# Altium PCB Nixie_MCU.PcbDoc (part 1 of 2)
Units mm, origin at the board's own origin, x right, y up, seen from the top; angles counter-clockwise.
Board outline 188 x 42 mm, 4 copper layers (Signal Layer 1, Layer 1, Layer 2, Bottom Layer), stack 1.466 mm thick; 180 components, 100 nets, 460 pads, 258 vias.
Unrouted connection lines stored in the file: 2.
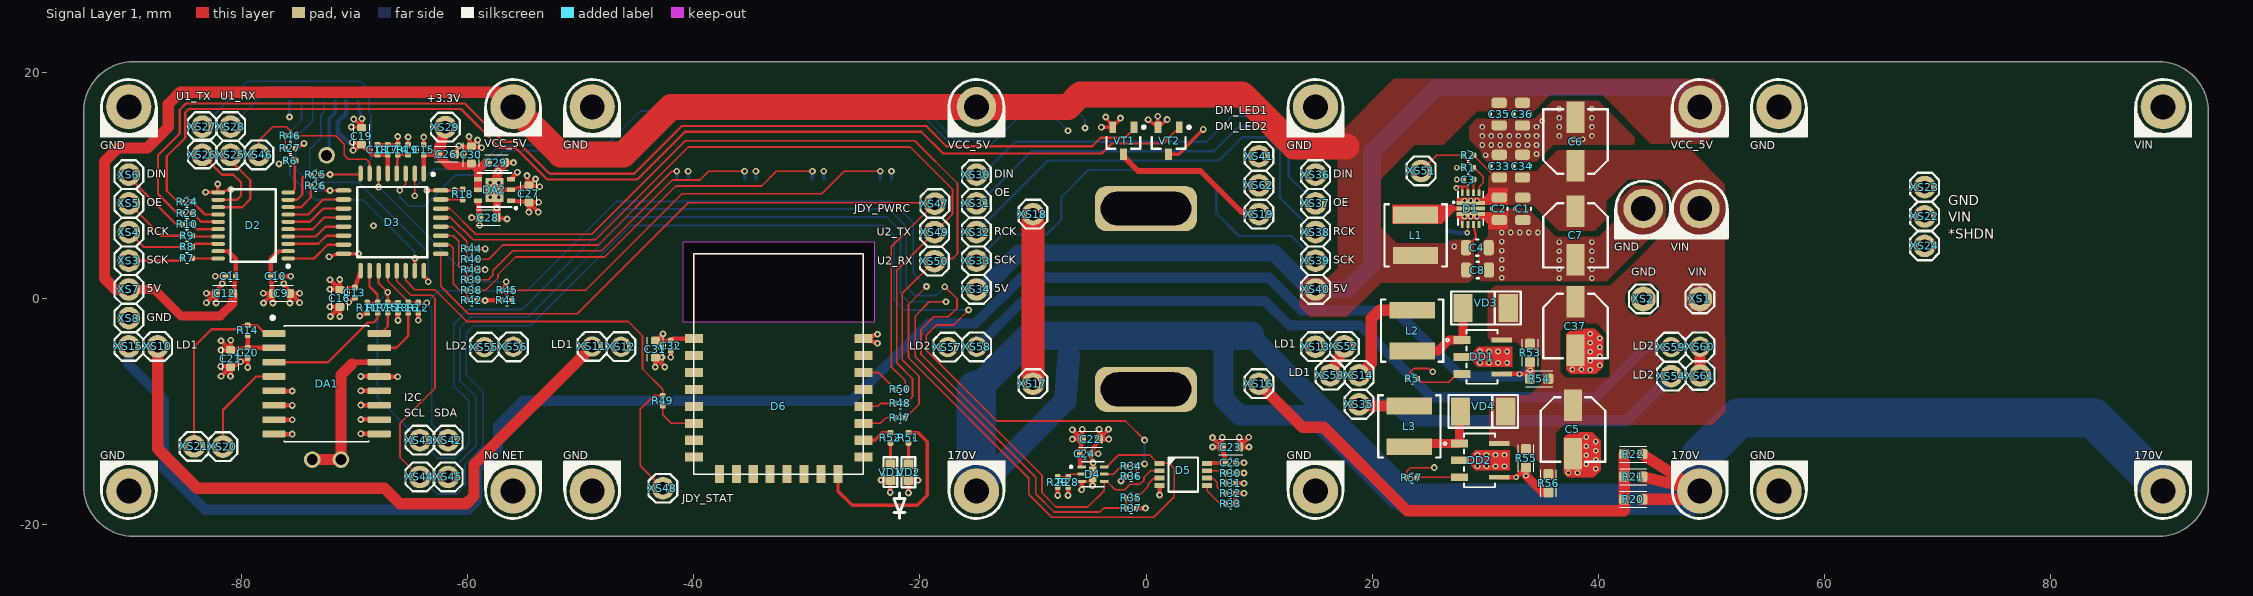
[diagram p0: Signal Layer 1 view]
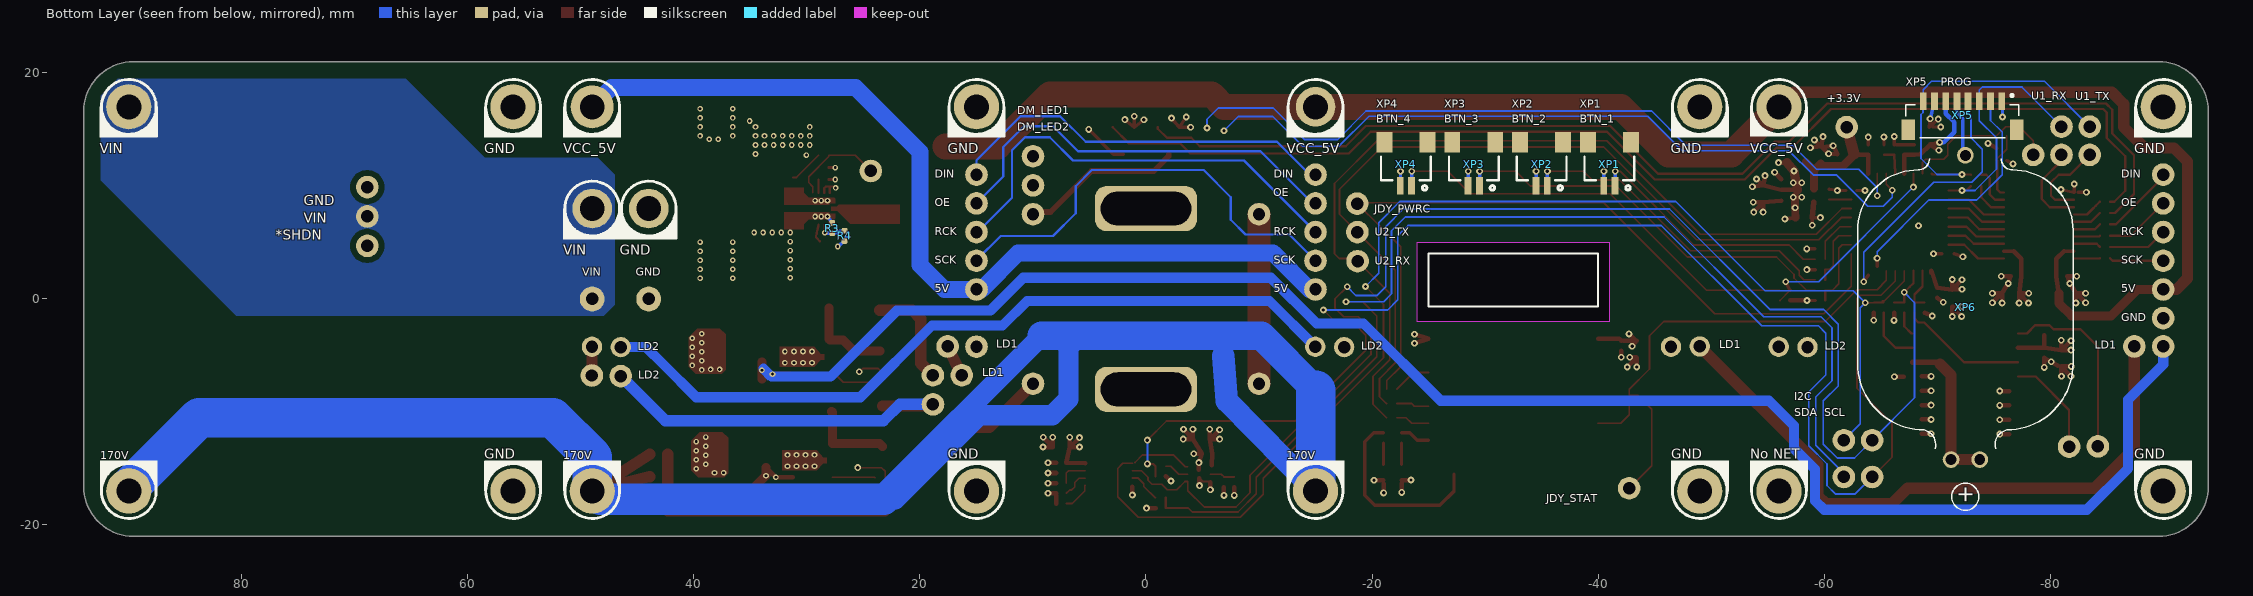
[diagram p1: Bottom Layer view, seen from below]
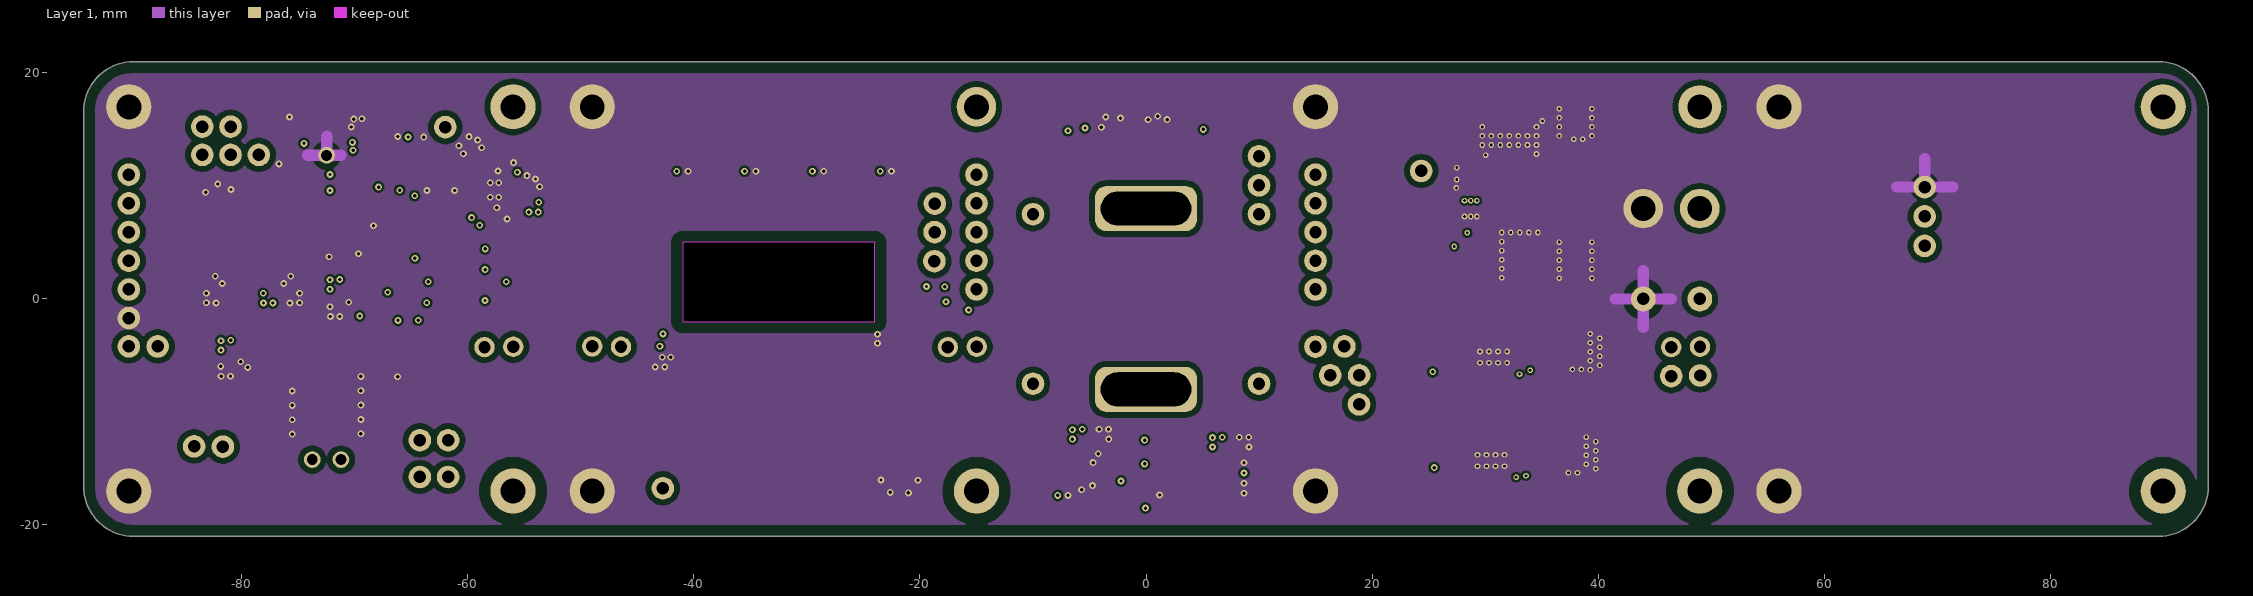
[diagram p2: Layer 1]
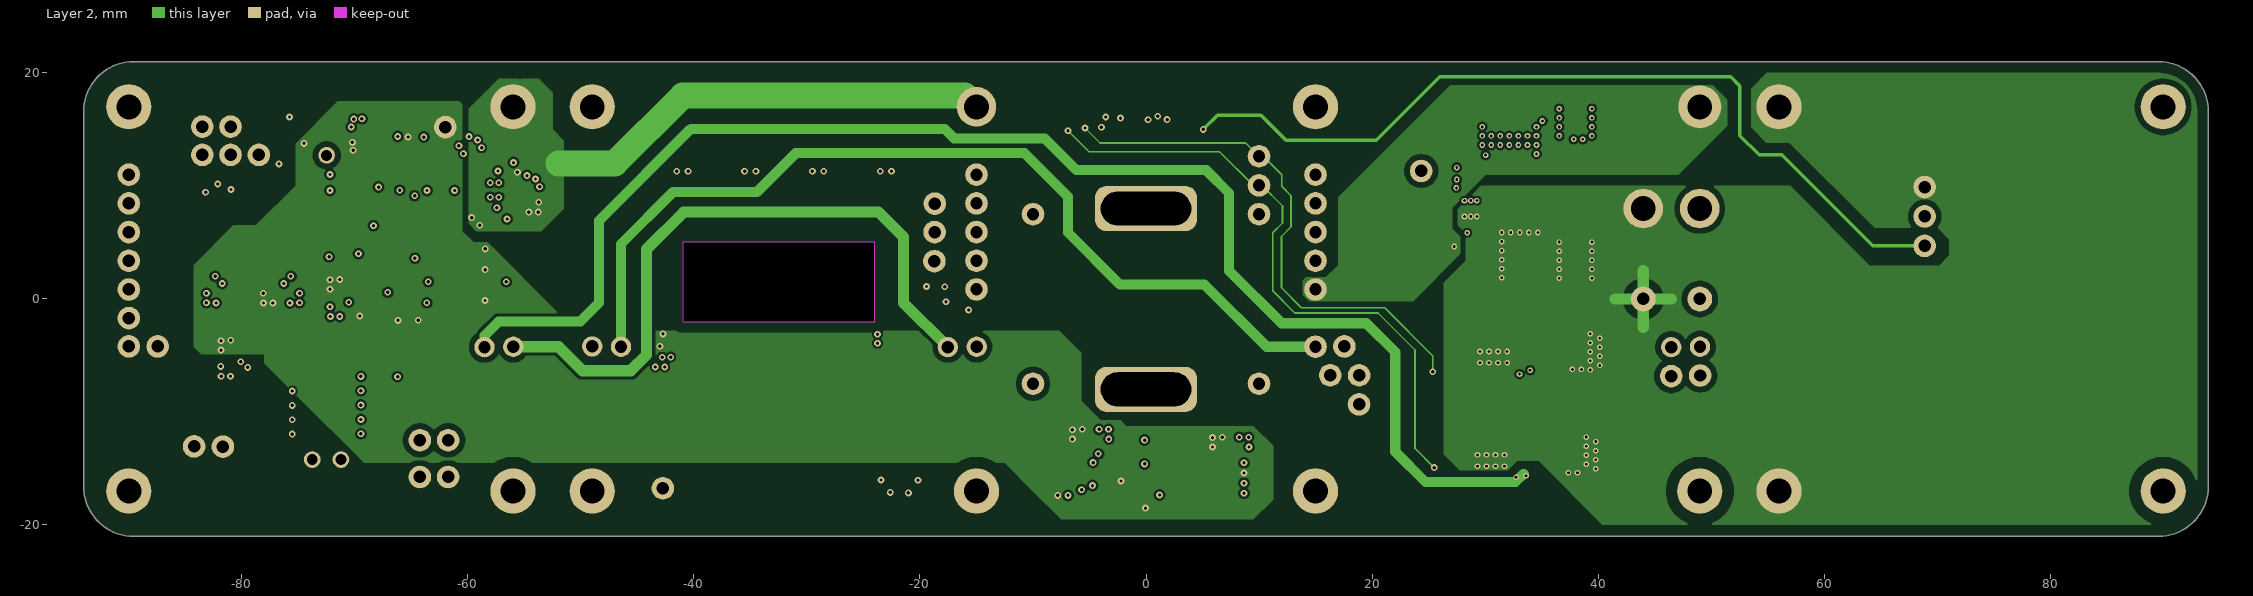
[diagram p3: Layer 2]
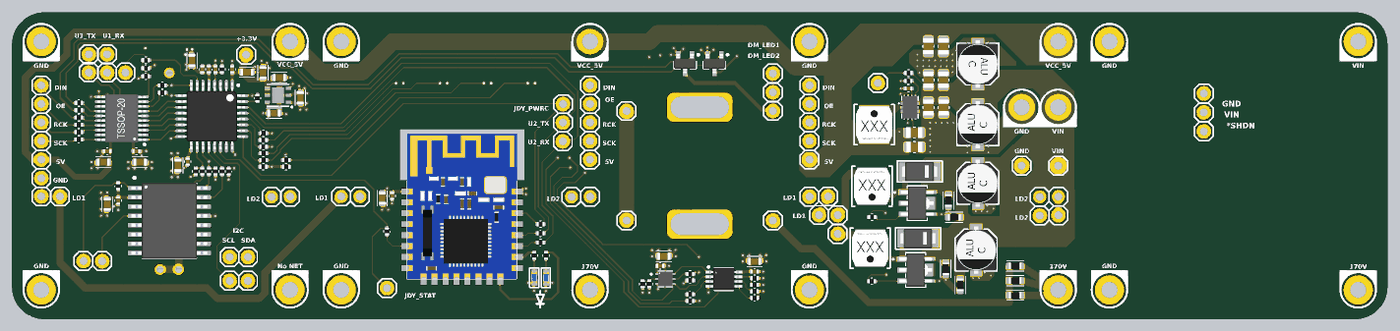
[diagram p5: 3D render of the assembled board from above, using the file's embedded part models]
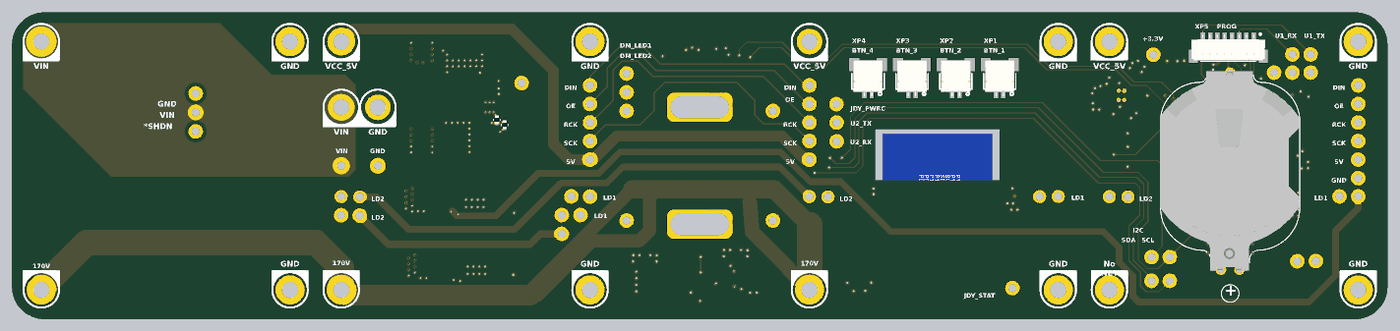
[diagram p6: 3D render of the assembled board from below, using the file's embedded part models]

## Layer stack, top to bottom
Top Solder: solder mask 0.01, Solder Resist, Dk 3.5
Signal Layer 1: signal copper 0.018
Dielectric 2: prepreg 0.115, FR4 2116, Dk 4.2
Layer 1: signal copper 0.018
Dielectric 1: core 1.164, FR4 Tg150, Dk 4.1
Layer 2: signal copper 0.018
Dielectric 3: prepreg 0.115, FR4 2116, Dk 4.1
Bottom Layer: signal copper 0.018
Bottom Solder: solder mask 0.01, Solder Resist, Dk 3.5

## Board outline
-94,-16.586 ccw(c-89.586,-16.586) -89.586,-21 89.586,-21 ccw(c89.586,-16.586) 94,-16.586 94,16.586 ccw(c89.586,16.586) 89.586,21 -89.586,21 ccw(c-89.586,16.586) -94,16.586
cut-out: -41,-2 -24,-2 -24,5 -41,5

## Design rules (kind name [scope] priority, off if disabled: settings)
BoardOutlineClearance [All] p1: gap=1 ignorepadtopadclearanceinfootprint=FALSE
Clearance [All] p1: gap=0.3 ignorepadtopadclearanceinfootprint=FALSE except(0.15: SMDPad-SMDPad SMDPad-THPad SMDPad-Via SMDPad-Fill SMDPad-Poly SMDPad-Region SMDPad-Text SMDPad-Hole; 0.2: Arc-SMDPad Track-SMDPad Via-Via Via-Fill Via-Poly Via-Region Via-Text Via-Hole Fill-Fill Fill-Poly Fill-Region Poly-Poly Poly-Region Region-Region; 0.25: Fill-Text Fill-Hole Poly-Text Poly-Hole Region-Text Region-Hole Text-Text Text-Hole; 0.5: THPad-THPad THPad-Via THPad-Fill THPad-Poly THPad-Region THPad-Text THPad-Hole)
ComponentClearance [All] p1: gap=0 collisioncheckmode=3 verticalgap=0 showdistances=FALSE
DiffPairsRouting [All] p1: maxlimit=0.254 minlimit=0.254 mostfreqgap=0.254 substack1={13A373E5-A3F0-4F58-9A2E-6A10E35ADB22} toplayer_{13a373e5-a3f0-4f58-9a2e-6a10e35adb22}_minwidth=0.381 toplayer_{13a373e5-a3f0-4f58-9a2e-6a10e35adb22}_maxwidth=0.381 toplayer_{13a373e5-a3f0-4f58-9a2e-6a10e35adb22}_prefwidth=0.381 midlayer1_{13a373e5-a3f0-4f58-9a2e-6a10e35adb22}_minwidth=0.381 midlayer1_{13a373e5-a3f0-4f58-9a2e-6a10e35adb22}_maxwidth=0.381 midlayer1_{13a373e5-a3f0-4f58-9a2e-6a10e35adb22}_prefwidth=0.381 midlayer2_{13a373e5-a3f0-4f58-9a2e-6a10e35adb22}_minwidth=0.381 midlayer2_{13a373e5-a3f0-4f58-9a2e-6a10e35adb22}_maxwidth=0.381 midlayer2_{13a373e5-a3f0-4f58-9a2e-6a10e35adb22}_prefwidth=0.381 bottomlayer_{13a373e5-a3f0-4f58-9a2e-6a10e35adb22}_minwidth=0.381 bottomlayer_{13a373e5-a3f0-4f58-9a2e-6a10e35adb22}_maxwidth=0.381 bottomlayer_{13a373e5-a3f0-4f58-9a2e-6a10e35adb22}_prefwidth=0.381 toplayer_minwidth=0.381 toplayer_maxwidth=0.381 toplayer_prefwidth=0.381 midlayer1_minwidth=0.381 midlayer1_maxwidth=0.381 midlayer1_prefwidth=0.381 midlayer2_minwidth=0.381 midlayer2_maxwidth=0.381 midlayer2_prefwidth=0.381 bottomlayer_minwidth=0.381 bottomlayer_maxwidth=0.381 bottomlayer_prefwidth=0.381 substack2={8E264451-6B6F-4AEF-BE25-3FA629468181} toplayer_{8e264451-6b6f-4aef-be25-3fa629468181}_minwidth=0.381 toplayer_{8e264451-6b6f-4aef-be25-3fa629468181}_maxwidth=0.381 toplayer_{8e264451-6b6f-4aef-be25-3fa629468181}_prefwidth=0.381 midlayer1_{8e264451-6b6f-4aef-be25-3fa629468181}_minwidth=0.381 midlayer1_{8e264451-6b6f-4aef-be25-3fa629468181}_maxwidth=0.381 midlayer1_{8e264451-6b6f-4aef-be25-3fa629468181}_prefwidth=0.381 midlayer2_{8e264451-6b6f-4aef-be25-3fa629468181}_minwidth=0.381 midlayer2_{8e264451-6b6f-4aef-be25-3fa629468181}_maxwidth=0.381 midlayer2_{8e264451-6b6f-4aef-be25-3fa629468181}_prefwidth=0.381 bottomlayer_{8e264451-6b6f-4aef-be25-3fa629468181}_minwidth=0.381 bottomlayer_{8e264451-6b6f-4aef-be25-3fa629468181}_maxwidth=0.381 bottomlayer_{8e264451-6b6f-4aef-be25-3fa629468181}_prefwidth=0.381 substack3={4B01B843-C838-4E2A-A504-E6D8B842CAE6} toplayer_{4b01b843-c838-4e2a-a504-e6d8b842cae6}_minwidth=0.381 toplayer_{4b01b843-c838-4e2a-a504-e6d8b842cae6}_maxwidth=0.381 toplayer_{4b01b843-c838-4e2a-a504-e6d8b842cae6}_prefwidth=0.381 midlayer1_{4b01b843-c838-4e2a-a504-e6d8b842cae6}_minwidth=0.381 midlayer1_{4b01b843-c838-4e2a-a504-e6d8b842cae6}_maxwidth=0.381 midlayer1_{4b01b843-c838-4e2a-a504-e6d8b842cae6}_prefwidth=0.381 midlayer2_{4b01b843-c838-4e2a-a504-e6d8b842cae6}_minwidth=0.381 midlayer2_{4b01b843-c838-4e2a-a504-e6d8b842cae6}_maxwidth=0.381 midlayer2_{4b01b843-c838-4e2a-a504-e6d8b842cae6}_prefwidth=0.381 bottomlayer_{4b01b843-c838-4e2a-a504-e6d8b842cae6}_minwidth=0.381 bottomlayer_{4b01b843-c838-4e2a-a504-e6d8b842cae6}_maxwidth=0.381 bottomlayer_{4b01b843-c838-4e2a-a504-e6d8b842cae6}_prefwidth=0.381 substack4={99483382-A1EF-4ECF-B319-A0B368B90AE1} toplayer_{99483382-a1ef-4ecf-b319-a0b368b90ae1}_minwidth=0.381 toplayer_{99483382-a1ef-4ecf-b319-a0b368b90ae1}_maxwidth=0.381 toplayer_{99483382-a1ef-4ecf-b319-a0b368b90ae1}_prefwidth=0.381 midlayer1_{99483382-a1ef-4ecf-b319-a0b368b90ae1}_minwidth=0.381 midlayer1_{99483382-a1ef-4ecf-b319-a0b368b90ae1}_maxwidth=0.381 midlayer1_{99483382-a1ef-4ecf-b319-a0b368b90ae1}_prefwidth=0.381 midlayer2_{99483382-a1ef-4ecf-b319-a0b368b90ae1}_minwidth=0.381 midlayer2_{99483382-a1ef-4ecf-b319-a0b368b90ae1}_maxwidth=0.381 midlayer2_{99483382-a1ef-4ecf-b319-a0b368b90ae1}_prefwidth=0.381 bottomlayer_{99483382-a1ef-4ecf-b319-a0b368b90ae1}_minwidth=0.381 bottomlayer_{99483382-a1ef-4ecf-b319-a0b368b90ae1}_maxwidth=0.381 bottomlayer_{99483382-a1ef-4ecf-b319-a0b368b90ae1}_prefwidth=0.381 substack5={F395EEA6-3FEA-43CE-B6E0-8CB6C0DE68A3} toplayer_{f395eea6-3fea-43ce-b6e0-8cb6c0de68a3}_minwidth=0.381 toplayer_{f395eea6-3fea-43ce-b6e0-8cb6c0de68a3}_maxwidth=0.381 toplayer_{f395eea6-3fea-43ce-b6e0-8cb6c0de68a3}_prefwidth=0.381 midlayer1_{f395eea6-3fea-43ce-b6e0-8cb6c0de68a3}_minwidth=0.381 midlayer1_{f395eea6-3fea-43ce-b6e0-8cb6c0de68a3}_maxwidth=0.381 midlayer1_{f395eea6-3fea-43ce-b6e0-8cb6c0de68a3}_prefwidth=0.381 midlayer2_{f395eea6-3fea-43ce-b6e0-8cb6c0de68a3}_minwidth=0.381 midlayer2_{f395eea6-3fea-43ce-b6e0-8cb6c0de68a3}_maxwidth=0.381 midlayer2_{f395eea6-3fea-43ce-b6e0-8cb6c0de68a3}_prefwidth=0.381 bottomlayer_{f395eea6-3fea-43ce-b6e0-8cb6c0de68a3}_minwidth=0.381 bottomlayer_{f395eea6-3fea-43ce-b6e0-8cb6c0de68a3}_maxwidth=0.381 bottomlayer_{f395eea6-3fea-43ce-b6e0-8cb6c0de68a3}_prefwidth=0.381 maxuncoupledlength=12.7
Height [All] p1: minheight=0 maxheight=1000 prefheight=0
MinimumSolderMaskSliver [All] p1: minsoldermaskwidth=0.2
PlaneClearance [All] p1: clearance=0.5
PlaneConnect [All] p1: planeconnectstyle=Relief reliefexpansion=0.5 reliefentries=4 reliefconductorwidth=0.25 reliefairgap=0.25
PolygonConnect PolygonConnect_VIA [IsVia] p1: connectstyle=Direct reliefconductorwidth=0.3 reliefentries=4 polygonreliefangle="45 Angle" airgapwidth=0.25
PolygonConnect [All] p2: connectstyle=Direct reliefconductorwidth=0.3 reliefentries=4 polygonreliefangle="90 Angle" airgapwidth=0.25
RoutingCorners [All] p1: cornerstyle=45-Degree minsetback=2.5 maxsetback=2.5
RoutingVias [All] p1: holewidth=0.3 width=0.6 viastyle="Through Hole" minholewidth=0.2 minwidth=0.5 maxholewidth=0.7 maxwidth=1.2
SilkToSilkClearance [All] p1: silktosilkclearance=0.2
SilkToSolderMaskClearance [IsPad] p1: minsilkscreentomaskgap=0.2 clearancetoexposedcopper=TRUE
SolderMaskExpansion [All] p1: expansion=0.075 istentingtop=FALSE
Width [All] p1: maxlimit=10 minlimit=0.125 preferedwidth=0.25 substack1={13A373E5-A3F0-4F58-9A2E-6A10E35ADB22} toplayer_{13a373e5-a3f0-4f58-9a2e-6a10e35adb22}_minwidth=0.15 toplayer_{13a373e5-a3f0-4f58-9a2e-6a10e35adb22}_maxwidth=2.5 midlayer1_{13a373e5-a3f0-4f58-9a2e-6a10e35adb22}_minwidth=0.15 midlayer1_{13a373e5-a3f0-4f58-9a2e-6a10e35adb22}_maxwidth=2.5 midlayer2_{13a373e5-a3f0-4f58-9a2e-6a10e35adb22}_minwidth=0.15 midlayer2_{13a373e5-a3f0-4f58-9a2e-6a10e35adb22}_maxwidth=2.5 bottomlayer_{13a373e5-a3f0-4f58-9a2e-6a10e35adb22}_minwidth=0.15 bottomlayer_{13a373e5-a3f0-4f58-9a2e-6a10e35adb22}_maxwidth=2.5 substack2={8E264451-6B6F-4AEF-BE25-3FA629468181} toplayer_{8e264451-6b6f-4aef-be25-3fa629468181}_minwidth=0.15 toplayer_{8e264451-6b6f-4aef-be25-3fa629468181}_maxwidth=2.5 midlayer1_{8e264451-6b6f-4aef-be25-3fa629468181}_minwidth=0.15 midlayer1_{8e264451-6b6f-4aef-be25-3fa629468181}_maxwidth=2.5 midlayer2_{8e264451-6b6f-4aef-be25-3fa629468181}_minwidth=0.15 midlayer2_{8e264451-6b6f-4aef-be25-3fa629468181}_maxwidth=2.5 bottomlayer_{8e264451-6b6f-4aef-be25-3fa629468181}_minwidth=0.15 bottomlayer_{8e264451-6b6f-4aef-be25-3fa629468181}_maxwidth=2.5 substack3={4B01B843-C838-4E2A-A504-E6D8B842CAE6} toplayer_{4b01b843-c838-4e2a-a504-e6d8b842cae6}_minwidth=0.15 toplayer_{4b01b843-c838-4e2a-a504-e6d8b842cae6}_maxwidth=2.5 midlayer1_{4b01b843-c838-4e2a-a504-e6d8b842cae6}_minwidth=0.15 midlayer1_{4b01b843-c838-4e2a-a504-e6d8b842cae6}_maxwidth=2.5 midlayer2_{4b01b843-c838-4e2a-a504-e6d8b842cae6}_minwidth=0.15 midlayer2_{4b01b843-c838-4e2a-a504-e6d8b842cae6}_maxwidth=2.5 bottomlayer_{4b01b843-c838-4e2a-a504-e6d8b842cae6}_minwidth=0.15 bottomlayer_{4b01b843-c838-4e2a-a504-e6d8b842cae6}_maxwidth=2.5 substack4={99483382-A1EF-4ECF-B319-A0B368B90AE1} toplayer_{99483382-a1ef-4ecf-b319-a0b368b90ae1}_minwidth=0.15 toplayer_{99483382-a1ef-4ecf-b319-a0b368b90ae1}_maxwidth=2.5 midlayer1_{99483382-a1ef-4ecf-b319-a0b368b90ae1}_minwidth=0.15 midlayer1_{99483382-a1ef-4ecf-b319-a0b368b90ae1}_maxwidth=2.5 midlayer2_{99483382-a1ef-4ecf-b319-a0b368b90ae1}_minwidth=0.15 midlayer2_{99483382-a1ef-4ecf-b319-a0b368b90ae1}_maxwidth=2.5 bottomlayer_{99483382-a1ef-4ecf-b319-a0b368b90ae1}_minwidth=0.15 bottomlayer_{99483382-a1ef-4ecf-b319-a0b368b90ae1}_maxwidth=2.5 substack5={F395EEA6-3FEA-43CE-B6E0-8CB6C0DE68A3} toplayer_{f395eea6-3fea-43ce-b6e0-8cb6c0de68a3}_minwidth=0.15 toplayer_{f395eea6-3fea-43ce-b6e0-8cb6c0de68a3}_maxwidth=2.5 midlayer1_{f395eea6-3fea-43ce-b6e0-8cb6c0de68a3}_minwidth=0.15 midlayer1_{f395eea6-3fea-43ce-b6e0-8cb6c0de68a3}_maxwidth=2.5 midlayer2_{f395eea6-3fea-43ce-b6e0-8cb6c0de68a3}_minwidth=0.15 midlayer2_{f395eea6-3fea-43ce-b6e0-8cb6c0de68a3}_maxwidth=2.5 bottomlayer_{f395eea6-3fea-43ce-b6e0-8cb6c0de68a3}_minwidth=0.15 bottomlayer_{f395eea6-3fea-43ce-b6e0-8cb6c0de68a3}_maxwidth=2.5
21 further rules are at their usual default settings.

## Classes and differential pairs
component class Nixie_MCU: C9 C10 C11 C12 C14 C20 C21 C22 C23 C24 C25 C31 C32 D2 D3 D4 D5 D6 DA1 R6 R7 R8 R9 R10 R11 R12 R13 R14 R15 R16 R17 R18 R19 R25 R26 R27 R28 R29 R30 R31 R32 R33 R34 R35 R36 R37 R38 R39 R40 R41 R42 R43 R44 R45 R46 R47 R48 R49 R50 R51 R52 VD1 VD2 XP1 XP2 XP3 XP4 XP5 XP6 XS3 XS4 XS5 XS6 XS20 XS21 XS25 XS26 XS27 XS28 XS30 XS31 XS32 XS33 XS34 XS36 XS37 XS38 XS39 XS40 XS42 XS43 XS44 XS45 XS46 XS47 XS48 XS49 XS50
component class Nixie_MCU_PWR: C1 C2 C3 C4 C5 C6 C7 C8 C13 C15 C16 C17 C18 C19 C26 C27 C28 C29 C30 C33 C34 C35 C36 C37 D1 DA2 DD1 DD2 L1 L2 L3 R1 R2 R3 R4 R5 R20 R21 R22 R23 R24 R53 R54 R55 R56 R57 VD3 VD4 VT1 VT2 XS1 XS2 XS7 XS8 XS10 XS11 XS12 XS13 XS14 XS15 XS16 XS17 XS18 XS19 XS22 XS23 XS24 XS29 XS35 XS41 XS51 XS52 XS53 XS54 XS55 XS56 XS57 XS58 XS59 XS60 XS61 XS62

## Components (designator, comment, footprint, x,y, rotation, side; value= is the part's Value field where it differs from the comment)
C1 "" "CAP: 0805R" 33.342,7.978 r90 top value="22 мкФ"
C2 "" "CAP: 0805R" 31.256,7.979 r90 top value="22 мкФ"
C3 "Ceramic capacitor, 2200 пФ, X7R, ± 10 %, , 0402, -55...+125°C" "CAP: 0402R" 28.523,10.568 r0 top value="2200 пФ"
C4 "" "CAP: 0805R" 29.32,4.538 r180 top value="22 мкФ"
C5 "Aluminium capacitor, 100 мкФ, , ±20%, , 5×5×5.3, -55...+105°C" "CAP: D5H5.8" 37.775,-11.55 r270 top value="100 мкФ"
C6 "Aluminium capacitor, 100 мкФ, , ±20%, , 5×5×5.3, -55...+105°C" "CAP: D5H5.8" 38.01,13.924 r90 top value="100 мкФ"
C7 "Aluminium capacitor, 100 мкФ, , ±20%, , 5×5×5.3, -55...+105°C" "CAP: D5H5.8" 38.01,5.625 r270 top value="100 мкФ"
C8 "" "CAP: 0805R" 29.338,2.558 r180 top value="22 мкФ"
C9 "Ceramic capacitor, 2,2 мкФ, X7R, ±10%, 16V, 0603, -55...+125°C" "CAP: 0603R" -76.5,0.5 r0 top value="2,2 мкФ"
C10 "Ceramic capacitor, 0,1 мкФ, X7R, ± 10 %, , 0402, -55...+125°C" "CAP: 0402R" -77,2 r180 top value="0,1 мкФ"
C11 "Ceramic capacitor, 0,1 мкФ, X7R, ± 10 %, , 0402, -55...+125°C" "CAP: 0402R" -81,2 r0 top value="0,1 мкФ"
C12 "Ceramic capacitor, 2,2 мкФ, X7R, ±10%, 16V, 0603, -55...+125°C" "CAP: 0603R" -81.525,0.5 r180 top value="2,2 мкФ"
C13 "Ceramic capacitor, 0,1 мкФ, X7R, ± 10 %, , 0402, -55...+125°C" "CAP: 0402R" -69.994,0.559 r90 top value="0,1 мкФ"
C14 "Ceramic capacitor, 0,1 мкФ, X7R, ± 10 %, , 0402, -55...+125°C" "CAP: 0402R" -66.2,13.2 r270 top value="0,1 мкФ"
C15 "Ceramic capacitor, 0,1 мкФ, X7R, ± 10 %, , 0402, -55...+125°C" "CAP: 0402R" -63.907,13.198 r270 top value="0,1 мкФ"
C16 "Ceramic capacitor, 10 мкФ, X7R, ±10%, 16V, 0603, -55...+125°C" "CAP: 0603R" -71.334,0.055 r270 top value="10 мкФ"
C17 "Ceramic capacitor, 10 нФ, X7R, ± 10 %, , 0402, -55...+125°C" "CAP: 0402R" -67.1,13.2 r270 top value="10 нФ"
C18 "Ceramic capacitor, 0,1 мкФ, X7R, ± 10 %, , 0402, -55...+125°C" "CAP: 0402R" -68,13.2 r270 top value="0,1 мкФ"
C19 "Ceramic capacitor, 10 мкФ, X7R, ±10%, 16V, 0603, -55...+125°C" "CAP: 0603R" -69.4,14.4 r90 top value="10 мкФ"
C20 "Ceramic capacitor, 0,1 мкФ, X7R, ± 10 %, , 0402, -55...+125°C" "CAP: 0402R" -79.485,-4.772 r90 top value="0,1 мкФ"
C21 "Ceramic capacitor, 2,2 мкФ, X7R, ±10%, 16V, 0603, -55...+125°C" "CAP: 0603R" -80.985,-5.272 r270 top value="2,2 мкФ"
C22 "Ceramic capacitor, 2,2 мкФ, X7R, ±10%, 16V, 0603, -55...+125°C" "CAP: 0603R" -4.9,-12.4 r0 top value="2,2 мкФ"
C23 "Ceramic capacitor, 2,2 мкФ, X7R, ±10%, 16V, 0603, -55...+125°C" "CAP: 0603R" 7.5,-13.1 r0 top value="2,2 мкФ"
C24 "Ceramic capacitor, 0,1 мкФ, X7R, ± 10 %, , 0402, -55...+125°C" "CAP: 0402R" -5.4,-13.7 r180 top value="0,1 мкФ"
C25 "Ceramic capacitor, 0,1 мкФ, X7R, ± 10 %, , 0402, -55...+125°C" "CAP: 0402R" 7.5,-14.5 r180 top value="0,1 мкФ"
C26 "Ceramic capacitor, 10 мкФ, X7R, ±10%, 16V, 0603, -55...+125°C" "CAP: 0603R" -61.899,12.82 r0 top value="10 мкФ"
C27 "Ceramic capacitor, 10 мкФ, X7R, ±10%, 16V, 0603, -55...+125°C" "CAP: 0603R" -54.6,9.3 r90 top value="10 мкФ"
C28 "Ceramic capacitor, 10 мкФ, X7R, ±10%, 16V, 0603, -55...+125°C" "CAP: 0603R" -58.2,7.2 r0 top value="10 мкФ"
C29 "Ceramic capacitor, 10 мкФ, X7R, ±10%, 16V, 0603, -55...+125°C" "CAP: 0603R" -57.473,12.073 r0 top value="10 мкФ"
C30 "Ceramic capacitor, 10 мкФ, X7R, ±10%, 16V, 0603, -55...+125°C" "CAP: 0603R" -59.7,12.75 r90 top value="10 мкФ"
C31 "Ceramic capacitor, 2,2 мкФ, X7R, ±10%, 16V, 0603, -55...+125°C" "CAP: 0603R" -43.416,-4.44 r270 top value="2,2 мкФ"
C32 "Ceramic capacitor, 0,1 мкФ, X7R, ± 10 %, , 0402, -55...+125°C" "CAP: 0402R" -42.04,-4.129 r90 top value="0,1 мкФ"
C33 "" "CAP: 0805R" 31.267,11.755 r270 top value="22 мкФ"
C34 "" "CAP: 0805R" 33.307,11.755 r270 top value="22 мкФ"
C35 "" "CAP: 0805R" 31.247,16.361 r90 top value="22 мкФ"
C36 "" "CAP: 0805R" 33.307,16.356 r90 top value="22 мкФ"
C37 "Aluminium capacitor, 100 мкФ, , ±20%, , 5×5×5.3, -55...+105°C" "CAP: D5H5.8" 38,-2.4 r270 top value="100 мкФ"
D1 "DC/DC buck converter, 3 V to 17 V, 1.25 or 2.5MHz, 0.8 V to 12 V, 2A, -40...+85°C, 3-mm x 2-mm VQFN" 11-VQFN(RGX) 28.727,8 r0 top
D2 "8-Bit Bidirectional Voltage-Level Translator, 24 Mbps, , 1.2 V to 3.6 V on A port and 1.65 V to 5.5 V on B, -40...+105°C, 20-TSSOP" 20-TSSOP -79,6.5 r180 top
D3 "IC microcontroller, 32-Bit, Cortex-M0, 48MHz, 32KB, 4KB, 2.4...3.6V, -40...+85°C, 32-LQFP" 32-LQFP -66.7,6.8 r270 top locked
D4 "Ambient Light Sensor, 1.6 V to 3.6 V, , , , -40…+85, USON (6)" "6-USON (OPT)" -4.7,-15.5 r0 top
D5 "Digital Temperature Sensor, 2.7V to 5.5V, , , , -40…+85, MSOP-8" 8-MSOP 1.2,-14.55 r270 top
D6 "bluetooth module, , , , -40...+85°C," "MOD: JDY-25M" -40,-15.5 r0 top locked
DA1 "Standard Clock Oscillators, , 15pF, ±50ppm, 7*5mm, -40...+85°C" 16-SOIC -72.5,-7.5 r0 top locked
DA2 "LP38693SD-3.3/NOPB" 6-WSON -57.647,9.642 r270 top
DD1 "LED current driver, 6 V to 30 v, , , 1.2A, -40…+125, SOT89-5" 5-SOT-89 29.728,-5.125 r270 top
DD2 "LED current driver, 6 V to 30 v, , , 1.2A, -40…+125, SOT89-5" 5-SOT-89 29.503,-14.275 r270 top
L1 "Fixed inductor, 2,2 мкГн, , , , -40...+125°C" "IND: VLS5045EX" 23.95,5.625 r90 top value="2,2 мкГн"
L2 "Fixed inductor, 100 мкГн, , , , -40...+125°C" "IND: VLS5045EX" 23.45,-2.8 r270 top value="100 мкГн"
L3 "Fixed inductor, 100 мкГн, , , , -40...+125°C" "IND: VLS5045EX" 23.2,-11.275 r270 top value="100 мкГн"
R1 "" "RES: 0402_ASK" 28.52,11.624 r180 top value="Не уст"
R2 "" "RES: 0402_ASK" 28.523,12.704 r180 top value="22 Ом"
R3 "" "RES: 0402_ASK" 27.75,6.275 r90 bottom value="150 кОм"
R4 "" "RES: 0402_ASK" 26.675,5.575 r90 bottom value="560 кОм"
R5 "" "RES: 0402_ASK" 23.55,-7.05 r0 top value="22 Ом"
R6 "" "RES: 0402_ASK" -75.7,12.25 r0 top value="20 кОм"
R7 "" "RES: 0402_ASK" -84.85,3.6 r180 top value="22 Ом"
R8 "" "RES: 0402_ASK" -84.85,4.6 r180 top value="22 Ом"
R9 "" "RES: 0402_ASK" -84.85,5.6 r180 top value="22 Ом"
R10 "" "RES: 0402_ASK" -84.85,6.6 r180 top value="22 Ом"
R11 "" "RES: 0402_ASK" -68.891,-0.77 r90 top value="10 кОм"
R12 "" "RES: 0402_ASK" -64.388,-0.769 r90 top value="10 кОм"
R13 "" "RES: 0402_ASK" -66.187,-0.774 r90 top value="10 кОм"
R14 "" "RES: 0402_ASK" -79.485,-2.772 r90 top value="10 кОм"
R15 "" "RES: 0402_ASK" -67.088,-0.764 r270 top value="22 Ом"
R16 "" "RES: 0402_ASK" -65.286,-0.768 r270 top value="22 Ом"
R17 "" "RES: 0402_ASK" -67.988,-0.766 r270 top value="22 Ом"
R18 "" "RES: 0402_ASK" -60.456,9.253 r90 top value="10 кОм"
R19 "" "RES: 0402_ASK" -65.3,13.2 r270 top value="10 кОм"
R20 "Resistor film, ?, ±1%, 0603, 0.1W, -55...+125°C" "RES: 0603_ASK" 42.325,-17.739 r0 top value=?
R21 "Resistor film, ?, ±1%, 0603, 0.1W, -55...+125°C" "RES: 0603_ASK" 42.325,-15.739 r0 top value=?
R22 "Resistor film, ?, ±1%, 0603, 0.1W, -55...+125°C" "RES: 0603_ASK" 42.325,-13.739 r0 top value=?
R23 "" "RES: 0402_ASK" -84.845,7.603 r0 top value="10 кОм"
R24 "" "RES: 0402_ASK" -84.847,8.606 r0 top value="10 кОм"
R25 "" "RES: 0402_ASK" -73.45,11 r180 top value="Не уст"
R26 "" "RES: 0402_ASK" -73.45,10 r180 top value="Не уст"
R27 "" "RES: 0402_ASK" -75.7,13.352 r0 top value="Не уст"
R28 "" "RES: 0402_ASK" -6.895,-16.196 r90 top value="22 Ом"
R29 "" "RES: 0402_ASK" -7.8,-16.2 r90 top value="Не уст"
R30 "" "RES: 0402_ASK" 7.5,-15.4 r0 top value="Не уст"
R31 "" "RES: 0402_ASK" 7.5,-16.3 r0 top value="22 Ом"
R32 "" "RES: 0402_ASK" 7.5,-17.2 r0 top value="22 Ом"
R33 "" "RES: 0402_ASK" 7.5,-18.1 r0 top value="22 Ом"
R34 "" "RES: 0402_ASK" -1.3,-14.8 r0 top value="22 Ом"
R35 "" "RES: 0402_ASK" -1.3,-17.6 r180 top value="22 Ом"
R36 "" "RES: 0402_ASK" -1.3,-15.7 r180 top value="10 кОм"
R37 "" "RES: 0402_ASK" -1.3,-18.5 r0 top value="10 кОм"
R38 "" "RES: 0402_ASK" -59.639,0.766 r180 top value="22 Ом"
R39 "" "RES: 0402_ASK" -59.644,1.688 r180 top value="22 Ом"
R40 "" "RES: 0402_ASK" -59.652,3.519 r180 top value="22 Ом"
R41 "" "RES: 0402_ASK" -56.549,-0.132 r0 top value="10 кОм"
R42 "" "RES: 0402_ASK" -59.652,-0.132 r180 top value="10 кОм"
R43 "" "RES: 0402_ASK" -59.65,2.6 r180 top value="10 кОм"
R44 "" "RES: 0402_ASK" -59.643,4.448 r180 top value="10 кОм"
R45 "" "RES: 0402_ASK" -56.537,0.772 r180 top value="22 Ом"
R46 "" "RES: 0402_ASK" -75.7,14.453 r0 top value="22 Ом"
R47 "" "RES: 0402_ASK" -21.75,-10.5 r180 top value="22 Ом"
R48 "" "RES: 0402_ASK" -21.75,-9.25 r180 top value="22 Ом"
R49 "" "RES: 0402_ASK" -42.75,-9 r270 top value="22 Ом"
R50 "" "RES: 0402_ASK" -21.75,-8 r180 top value="22 Ом"
R51 "" "RES: 0402_ASK" -21.011,-12.3 r90 top value="1 кОм"
R52 "" "RES: 0402_ASK" -22.61,-12.3 r90 top value="1 кОм"
R53 "Resistor film, ?, ±1%, 0603, 0.1W, -55...+125°C" "RES: 0603_ASK" 34,-5.55 r90 top value=?
R54 "Resistor film, ?, ±1%, 0603, 0.1W, -55...+125°C" "RES: 0603_ASK" 34,-7.075 r0 top value=?
R55 "Resistor film, ?, ±1%, 0603, 0.1W, -55...+125°C" "RES: 0603_ASK" 33.637,-14.889 r90 top value=?
R56 "Resistor film, ?, ±1%, 0603, 0.1W, -55...+125°C" "RES: 0603_ASK" 35.625,-17.1 r90 top value=?
R57 "" "RES: 0402_ASK" 23.525,-15.825 r0 top value="22 Ом"
VD1 "LED, *, *, *, -55...+150°C" "LED: 0603B" -22.61,-15.321 r270 top
VD2 "LED, *, *, *, -55...+150°C" "LED: 0603B" -21.011,-15.336 r270 top
VD3 "Schottky diode, 80V, 500mA, 1V, 15pF, SOD-123, -55...+150°C" "DIODE: SMA" 30.05,-0.8 r0 top
VD4 "Schottky diode, 80V, 500mA, 1V, 15pF, SOD-123, -55...+150°C" "DIODE: SMA" 29.825,-9.95 r0 top
VT1 "NPN transistor, 45V, 100mA, 100MHz, 300mW, 0.6V, 420, SOT-23, -55...+125°C" SOT23 -2,14 r270 top
VT2 "NPN transistor, 45V, 100mA, 100MHz, 300mW, 0.6V, 420, SOT-23, -55...+125°C" SOT23 2,14 r270 top
XP1 "Connector, 2pin, 0.8mm, 50VAC, 1A" "CON: SM02B-SRSS-TB" -41,13 r180 bottom
XP2 "Connector, 2pin, 0.8mm, 50VAC, 1A" "CON: SM02B-SRSS-TB" -35,13 r180 bottom
XP3 "Connector, 2pin, 0.8mm, 50VAC, 1A" "CON: SM02B-SRSS-TB" -29,13 r180 bottom
XP4 "Connector, 2pin, 0.8mm, 50VAC, 1A" "CON: SM02B-SRSS-TB" -23,13 r180 bottom
XP5 "BM08B-SRSS-TB" "CON: BM08B-SRSS-TB" -72.25,17.5 r0 bottom
XP6 "120591-1" "CON: 120591-1 (CR2032)" -72.5,-0.75 r90 bottom locked
XS1 "" "CON: PLD-1"#1 49,0 r0 top
XS2 "" "CON: PLD-1"#1 44,0 r0 top
XS3 "" "CON: PLD-1"#2 -90,3.38 r90 top
XS4 "" "CON: PLD-1"#2 -90,5.92 r90 top
XS5 "" "CON: PLD-1"#2 -90,8.46 r90 top
XS6 "" "CON: PLD-1"#2 -90,11 r90 top
XS7 "" "CON: PLD-1"#2 -90,0.84 r90 top
XS8 "" "CON: PLD-1"#2 -90,-1.7 r90 top
XS10 "" "CON: PLD-1"#2 -87.445,-4.203 r90 top
XS11 "" "CON: PLD-1"#3 -49,-4.2 r90 top
XS12 "" "CON: PLD-1"#3 -46.45,-4.225 r90 top
XS13 "" "CON: PLD-1"#2 15,-4.225 r90 top
XS14 "" "CON: PLD-1"#2 18.855,-6.753 r90 top
XS15 "" "CON: PLD-1"#2 -90,-4.2 r90 top
XS16 "" "CON: PLD-1"#2 10,-7.5 r270 top
XS17 "" "CON: PLD-1"#2 -10,-7.5 r270 top
XS18 "" "CON: PLD-1"#2 -10,7.5 r270 top
XS19 "" "CON: PLD-1"#2 10,7.5 r270 top
XS20 "" "CON: PLD-1"#2 -81.673,-13.067 r180 top
XS21 "" "CON: PLD-1"#2 -84.223,-13.045 r180 top
XS22 "" "CON: PLD-1"#2 68.9,7.3 r270 top
XS23 "" "CON: PLD-1"#2 68.9,9.9 r270 top
XS24 "" "CON: PLD-1"#2 68.9,4.7 r270 top
XS25 "" "CON: PLD-1"#2 -81,12.75 r0 top
XS26 "" "CON: PLD-1"#4 -83.5,12.825 r0 top
XS27 "" "CON: PLD-1"#2 -83.5,15.25 r0 top
XS28 "" "CON: PLD-1"#2 -81,15.25 r0 top
XS29 "" "CON: PLD-1"#2 -62,15.2 r90 top
XS30 "" "CON: PLD-1"#2 -15,11 r90 top
XS31 "" "CON: PLD-1"#2 -15,8.46 r90 top
XS32 "" "CON: PLD-1"#2 -15,5.92 r90 top
XS33 "" "CON: PLD-1"#2 -15,3.38 r90 top
XS34 "" "CON: PLD-1"#2 -15,0.84 r90 top
XS35 "" "CON: PLD-1"#2 18.85,-9.325 r90 top
XS36 "" "CON: PLD-1"#2 15,11 r90 top
XS37 "" "CON: PLD-1"#2 15,8.46 r90 top
XS38 "" "CON: PLD-1"#2 15,5.92 r90 top
XS39 "" "CON: PLD-1"#2 15,3.38 r90 top
XS40 "" "CON: PLD-1"#2 15,0.84 r90 top
XS41 "" "CON: PLD-1"#2 10,12.625 r90 top
XS42 "" "CON: PLD-1"#2 -61.75,-12.5 r90 top
XS43 "" "CON: PLD-1"#2 -64.25,-12.5 r90 top
XS44 "" "CON: PLD-1"#2 -64.25,-15.75 r90 top
XS45 "" "CON: PLD-1"#2 -61.75,-15.75 r90 top
XS46 "" "CON: PLD-1"#2 -78.5,12.75 r90 top
XS47 "" "CON: PLD-1"#2 -18.686,8.438 r90 top
XS48 "" "CON: PLD-1"#2 -42.75,-16.75 r90 top
XS49 "" "CON: PLD-1"#2 -18.706,5.913 r90 top
XS50 "" "CON: PLD-1"#2 -18.718,3.34 r90 top
XS51 "" "CON: PLD-1"#2 24.35,11.325 r90 top
XS52 "" "CON: PLD-1"#2 17.555,-4.203 r90 top
XS53 "" "CON: PLD-1"#2 16.3,-6.75 r90 top
XS54 "" "CON: PLD-1"#2 46.475,-6.825 r90 top
XS55 "" "CON: PLD-1"#3 -58.532,-4.262 r90 top
XS56 "" "CON: PLD-1"#3 -55.98,-4.231 r90 top
XS57 "" "CON: PLD-1"#3 -17.532,-4.262 r90 top
XS58 "" "CON: PLD-1"#3 -14.98,-4.231 r90 top
XS59 "" "CON: PLD-1"#3 46.468,-4.262 r90 top
XS60 "" "CON: PLD-1"#3 49.02,-4.231 r90 top
XS61 "" "CON: PLD-1"#2 49.025,-6.775 r90 top
XS62 "" "CON: PLD-1"#2 10,10.05 r90 top

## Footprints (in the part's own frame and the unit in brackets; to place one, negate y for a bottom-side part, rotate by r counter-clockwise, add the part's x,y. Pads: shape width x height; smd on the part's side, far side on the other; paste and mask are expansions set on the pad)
5-SOT-89 [mm]
  rect 0.7x1.5 smd: 1(-1.5,-1.753) 2(0,-1.753) 3(1.5,-1.753)
  rect 0.432x1.8 smd: 4(1.5,1.753) 5(-1.5,1.753)
  Signal Layer 1 region: 0.876,-0.356 0.241,-0.94 0.241,-1.245 -0.241,-1.245 -0.241,-0.94 -0.876,-0.356 -0.876,2.667 0.876,2.667
  silkscreen extent -2.37,-3.18 2.37,1.37, body extent -2.25,-2.25 2.25,2.25, height 1.8
"6-USON (OPT)" [mm]
  rrect25% 0.74x0.27 smd: 1(-0.995,0.65) 2(-0.995,0) 3(-0.995,-0.65) 4(0.995,-0.65) 5(0.995,0) 6(0.995,0.65)
  rect 0.65x1.35 smd paste-2: 7(0,0)
  silkscreen extent -2.03,-1.1 1,1.1, body extent -1,-1 1,1, height 0.65
6-WSON [mm]
  rect 0.4x0.7 smd mask+0.05: 1(0.95,1.45) 2(0,1.45) 3(-0.95,1.45) 4(-0.95,-1.45) 5(0,-1.45) 6(0.95,-1.45)
  rect 2.1x1.6 smd mask+0.075: 7(0,0)
  silkscreen extent -1.5,-1.5 1.7,2, body extent -1.5,-1.5 1.5,1.5, height 0.8
8-MSOP [mm] "pitch 0.65 mm"
  rect 0.42x0.89 smd: 1(0,0) 2(0.65,0) 3(1.3,0) 4(1.95,0) 5(1.95,4.19) 6(1.3,4.19) 7(0.65,4.19) 8(0,4.19)
  round 0.5 on Top Overlay: ""(-0.7,0)
  silkscreen extent -0.53,0.8 2.5,3.4, body extent -0.53,-0.35 2.48,4.55, height 1.15
11-VQFN(RGX) [mm]
  rect 2.5x0.35 smd: 1(0,0.5) 2(0,0) 3(0,-0.5)
  rect 0.25x0.6 smd: 4(-0.75,-1.4) 5(-0.25,-1.4) 6(0.25,-1.4) 7(0.75,-1.4) 8(0.75,1.4) 9(0.25,1.4) 10(-0.25,1.4) 11(-0.75,1.4)
  silkscreen extent -1.55,-1.47 1.12,1.5, body extent -1,-1.51 1,1.49, height 1
16-SOIC [mm] "pitch 1.27 mm"
  rrect25% 2.05x0.59 smd: 1(-4.655,4.445) 2(-4.655,3.175) 3(-4.655,1.905) 4(-4.655,0.635) 5(-4.655,-0.635) 6(-4.655,-1.905) 7(-4.655,-3.175) 8(-4.655,-4.445) 9(4.655,-4.445) 10(4.655,-3.175) 11(4.655,-1.905) 12(4.655,-0.635) 13(4.655,0.635) 14(4.655,1.905) 15(4.655,3.175) 16(4.655,4.445)
  silkscreen extent -4.87,-5.15 3.75,5.94, body extent -5.16,-5.15 5.16,5.15, height 2.65
20-TSSOP [mm] "pitch 0.65 mm"
  oval 1.2x0.35 smd: 1(-3.1,2.925) 2(-3.1,2.275) 3(-3.1,1.625) 4(-3.1,0.975) 5(-3.1,0.325) 6(-3.1,-0.325) 7(-3.1,-0.975) 8(-3.1,-1.625) 9(-3.1,-2.275) 10(-3.1,-2.925) 11(3.1,-2.925) 12(3.1,-2.275) 13(3.1,-1.625) 14(3.1,-0.975) 15(3.1,-0.325) 16(3.1,0.325) 17(3.1,0.975) 18(3.1,1.625) 19(3.1,2.275) 20(3.1,2.925)
  round 0.5 on Mech1: ""(-2.8,2.8)
  silkscreen extent -3.22,-3.2 2,3.72, body extent -3.3,-3.3 3.3,3.3, height 1.2
32-LQFP [mm] "pitch 0.8 mm"
  rrect100% 1.4x0.4 smd: 1(-4.3,2.8) 2(-4.3,2) 3(-4.3,1.2) 4(-4.3,0.4) 5(-4.3,-0.4) 6(-4.3,-1.2) 7(-4.3,-2) 8(-4.3,-2.8) 17(4.3,-2.8) 18(4.3,-2) 19(4.3,-1.2) 20(4.3,-0.4) 21(4.3,0.4) 22(4.3,1.2) 23(4.3,2) 24(4.3,2.8)
  rrect100% 0.4x1.4 smd: 9(-2.8,-4.3) 10(-2,-4.3) 11(-1.2,-4.3) 12(-0.4,-4.3) 13(0.4,-4.3) 14(1.2,-4.3) 15(2,-4.3) 16(2.8,-4.3) 25(2.8,4.3) 26(2,4.3) 27(1.2,4.3) 28(0.4,4.3) 29(-0.4,4.3) 30(-1.2,4.3) 31(-2,4.3) 32(-2.8,4.3)
  round 0.5 on Mech1: ""(-4,4)
  silkscreen extent -4.35,-3.1 3.1,3.75, body extent -4.57,-4.57 4.57,4.57, height 1.62
"CAP: 0402R" [mm] "Chip Capacitor, Body 1.0x0.5mm, IPC High Density"
  rrect40% 0.5x0.5 smd mask+0.075: 1(-0.45,0) 2(0.45,0)
  silkscreen extent -0.1,-0.45 0.1,0.45, body extent -0.53,-0.28 0.53,0.28, height 0.55
"CAP: 0603R" [mm]
  rrect43% 0.7x0.8 smd mask+0.1: 1(0.75,0) 2(-0.75,0)
  silkscreen extent -1.05,-0.7 1.05,0.7, body extent -0.88,-0.48 0.87,0.47, height 0.95
"CAP: 0805R" [mm] "Chip Capacitor, Body 2.0x1.3mm, PANTES land pattern"
  rrect50% 0.9x1.35 smd mask+0.075: 1(-1,0) 2(1,0)
  silkscreen extent -0.1,-0.72 0.1,0.72, body extent -1.1,-0.72 1.1,0.72, height 1.45
"CAP: D5H5.8" [mm] "Aluminum Capacitor, Body 5(D)x5.8(L)mm, Recommended land pattern"
  rect 2.8x1.6 smd mask+0.075: 1(-2.15,0) 2(2.15,0)
  silkscreen extent -2.85,-2.85 2.85,2.85, body extent -3.25,-2.8 3.25,2.8, height 6.1
"CON: 120591-1 (CR2032)" [mm] "CR2032 Holder"
  round 1.478 hole 0.97: 1(-13.46,-1.27) 1(-13.46,1.27) 2(13.46,0)
  silkscreen extent -17.95,-9.53 13.17,9.53, body extent -13.63,-9.43 13.67,9.62, height 6.12
"CON: BM08B-SRSS-TB" [mm]
  rect 0.6x1.55 smd: 1(-3.476,0) 2(-2.476,0) 3(-1.484,0) 4(-0.492,0) 5(0.5,0) 6(1.492,0) 7(2.484,0) 8(3.476,0)
  rect 1.2x1.8 smd: SH1(-4.776,2.525) SH2(4.792,2.525)
  silkscreen extent -4.98,-0.62 5.01,3.22, body extent -4.97,-0.53 5.03,3.08, height 4.25
"CON: PLD-1"#1 [mm]
  round 2.2 hole 1.1: 1(0,0)
  silkscreen extent -1.27,-1.27 1.27,1.27
"CON: PLD-1"#2 [mm]
  round 2 hole 1.1: 1(0,0)
  silkscreen extent -1.27,-1.27 1.27,1.27
"CON: PLD-1"#3 [mm]
  round 1.8 hole 1.1: 1(0,0)
  silkscreen extent -1.27,-1.27 1.27,1.27
"CON: PLD-1"#4 [mm]
  round 2 hole 1.1: 1(0,-0.075)
  silkscreen extent -1.27,-1.27 1.27,1.27
"CON: SM02B-SRSS-TB" [mm] "Угловой"
  rect 0.6x1.55 smd: 1(0.5,-3) 2(-0.5,-3)
  rect 1.4x1.8 smd: K1(-1.9,0.875) K2(1.9,0.875)
  silkscreen extent -2.2,-3.38 2.2,-0.4, body extent -2,-3.55 2,1.4, height 2.95
"DIODE: SMA" [mm]
  rect 1.7x2.5 smd: 1(-2,0) 2(2,0)
  round 0.5 on Mech1: ""(2,0.9)
  silkscreen extent -3.05,-1.45 3.1,1.45, body extent -2.5,-1.35 2.5,1.35, height 2.28
"IND: VLS5045EX" [mm]
  rect 1.5x4 smd paste+0 mask+0.075: 1(1.8,0.1) 2(-1.8,0.1)
  silkscreen extent -2.75,-2.65 2.75,2.85, body extent -2.5,-2.4 2.5,2.6, height 4.49
"LED: 0603B" [mm]
  rect 0.85x0.85 smd: 1(-0.7,0) 2(0.7,0)
  silkscreen extent -1.33,-0.63 1.33,0.6, body extent -0.8,-0.4 0.8,0.4, height 0.6
"MOD: JDY-25M" [mm] "3д это jdy8 по идее подойдет тоже"
  rect 1.6x0.8 smd: 1(0,12) 2(0,10.5) 3(0,9) 4(0,7.5) 5(0,6) 6(0,4.5) 7(0,3) 8(0,1.5) 17(15,1.5) 18(15,3) 19(15,4.5) 20(15,6) 21(15,7.5) 22(15,9) 23(15,10.5) 24(15,12)
  rect 0.8x1.6 smd: 9(2.25,0) 10(3.75,0) 11(5.25,0) 12(6.75,0) 13(8.25,0) 14(9.75,0) 15(11.25,0) 16(12.75,0)
  silkscreen extent 0,0 15,19.5, body extent 0,0 15.01,19.89, height 2.18
"RES: 0402_ASK" [mm] "Chip Resistor, Body 1.0x0.5mm, IPC High Density"
  rrect40% 0.5x0.5 smd mask+0.075: 1(-0.45,0) 2(0.45,0)
  silkscreen extent -0.1,-0.45 0.1,0.45, body extent -0.52,-0.27 0.53,0.28, height 0.37
"RES: 0603_ASK" [mm]
  rrect35% 0.9x0.9 smd mask+0.075: 1(-0.011,0.012) 2(1.589,0.012)
  silkscreen extent -0.41,-0.69 1.99,0.71, body extent -0.06,-0.44 1.64,0.46, height 0.55
SOT23 [mm]
  rect 1x0.6 smd: 1(-1.2,0.95) 2(-1.2,-0.95) 3(1.2,0)
  round 0.5 on Mech1: ""(-0.9,1.1)
  silkscreen extent -1.32,-1.5 0.7,1.92, body extent -1.32,-1.52 1.32,1.52, height 1.12

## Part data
C1 C2 C4 C8 C33 C34 C35 C36: library part Ceramic_0603, Package=0805, Temperature=-55...+125°C, Tolerance=±20%, TypeCapacitor="Ceramic capacitor", TypeDielectric=X5R, Volt=25В
C3: library part Ceramic_0402, Manufacturer=Murata, Package=0402, Temperature=-55...+125°C, Tolerance="± 10 %", TypeCapacitor="Ceramic capacitor", TypeDielectric=X7R, Volt="50 В"
C5 C6 C7 C37: library part Aluminium, Manufacturer=Panasonic, Package=5×5×5.3, PartNumber=EEE-FT1C101AR, Temperature=-55...+105°C, Tolerance=±20%, TypeCapacitor="Aluminium capacitor"
C9 C12 C16 C19 C21 C22 C23 C26 C27 C28 C29 C30 C31: library part Ceramic_0603, Manufacturer=Yageo, Package=0603, Temperature=-55...+125°C, Tolerance=±10%, TypeCapacitor="Ceramic capacitor", TypeDielectric=X7R, Voltage=16V
C10 C11 C13 C14 C15 C17 C18 C20 C24 C25 C32: library part Ceramic_0402, Manufacturer=Murata, Package=0402, PartNumber=GCM155R71H104KE02#, Temperature=-55...+125°C, Tolerance="± 10 %", TypeCapacitor="Ceramic capacitor", TypeDielectric=X7R, Volt="50 В"
D1: library part TPS62147RGX, "3-V to 17-V 2-A Step-Down Converters", CurrentOutput=2A, Frequency="1.25 or 2.5MHz", Manufacturer="Texas Instruments", Package="3-mm x 2-mm VQFN", Temperature=-40...+85°C, VoltageInput="3 V to 17 V", VoltageOutput="0.8 V to 12 V"
D2: library part TXS0108EPW, "Voltage-Level Translator", Manufacturer="Texas Instruments", Package=20-TSSOP, Temperature=-40...+105°C
D3: library part STM32F030K6T6, "Cortex-M0", Manufacturer=STMicroelectronics, Package=32-LQFP, PartNumber=STM32L031K6T6, Temperature=-40...+85°C
D4: library part OPT3001IDNPQ1, "Ambient Light Sensor", Manufacturer="Texas Instruments", Package="USON (6)", PartNumber=OPT3001DNP, Temperature=-40…+85, VoltageInput="1.6 V to 3.6 V"
D5: library part TMP75AIDGKT, "Digital Temperature Sensor", Manufacturer="Texas Instruments", Package=MSOP-8, Temperature=-40…+85, VoltageInput="2.7V to 5.5V"
D6: library part JDY-25M, "bluetooth module", Temperature=-40...+85°C
DA1: library part DS3231SN, LoadCapacitance=15pF, Manufacturer=Vectron, Package=7*5mm, PartNumber=VCC1-B3D-25M0000000, Temperature=-40...+85°C, Tolerance=±50ppm
DA2: "LINEAR 3.3V 500MA 6WSON", CurrentOutput="500 mA", Manufacturer="Texas Instruments", Package="WSON (6)", Temperature=-40…+125, ValueManufacturerPartNumber="LDO, (2.7 V to 10 V), , output 3.3V, 500 mA, -40…+125, WSON (6)", VoltageInput="(2.7 V to 10 V)", VoltageOutput="output 3.3V"
DD1 DD2: library part PT4115, "LED current driver", CurrentOutput=1.2A, Package=SOT89-5, Temperature=-40…+125, VoltageInput="6 V to 30 v"
L1: library part VLS5045EX, "Power Inductor, 5.0x5.0x4.5mm, -40°C to +105°C", PartNumber=VLS5045EX-2R2N, Temperature=-40...+125°C, TypeInductor="Fixed inductor"
L2 L3: library part VLS5045EX, "Power Inductor, 5.0x5.0x4.5mm, -40°C to +105°C", PartNumber=VLS5045EX-101M, Temperature=-40...+125°C, TypeInductor="Fixed inductor"
R1 R2 R3 R4 R23 R24: library part Resistor_0402, Package=0402, Power="0.063 Вт", Temperature=-55...+125°C, Tolerance=±1%, TypeResistor="Resistor film"
R5 R6 R7 R8 R9 R10 R11 R12 R13 R14 R15 R16 R17 R18 R19 R25 R26 R27 R28 R29 R30 R31 R32 R33 R34 R35 R36 R37 R38 R39 R40 R41 R42 R43 R44 R45 R46 R47 R48 R49 R50 R57: library part Resistor_0402, Package=0402, PartNumber_book="Электроэлемент, резистор RC0402FR-0710KL", Power="0.063 Вт", Temperature=-55...+125°C, Tolerance=±1%, TypeResistor="Resistor film"
R20 R21 R22 R53 R54 R55 R56: library part Resistor_0603, Manufacturer=Yageo, Package=0603, PartNumber=RC0603JR-07100RL, Power=0.1W, Temperature=-55...+125°C, Tolerance=±1%, TypeResistor="Resistor film"
R51 R52: library part Resistor_0402, Manufacturer=TYCO, Package=0402, PartNumber=1676480-3, PartNumber_book="Электроэлемент, резистор RC0402FR-0710KL", Power="0.063 Вт", Temperature=-55...+125°C, Tolerance=±1%, TypeResistor="Resistor film"
VD1 VD2: library part LED_Salut_V1, Temperature=-55...+150°C
VD3 VD4: library part Schottky_single, Current=500mA, Manufacturer="Diodes Incorporated", Package=SOD-123, PartNumber=SS14H, Temperature=-55...+150°C, Voltage=80V, VoltageDrop=1V
VT1 VT2: library part BJT_NPN_132, CurrentCE=100mA, CurrentGain=420, Frequency=100MHz, Manufacturer="ON Semiconductor", MaxPower=300mW, Package=SOT-23, PartNumber=MMBTA42, Temperature=-55...+125°C, VoltageCE=45V, VoltageSaturation=0.6V
XP1 XP2 XP3 XP4: library part SM02B-SRSS-TB, CurrentMax=1A, Manufacturer=JST, VoltageMax=50VAC
XP5: CurrentMax=3A, Manufacturer=jst, ValueManufacturerPartNumber="Connector, 8pin, , 250VAC, 3A", VoltageMax=250VAC
XP6: "CR2032 Holder", CurrentMax=3A, Manufacturer=jst, ValueManufacturerPartNumber="Connector, 2pin, , 250VAC, 3A", VoltageMax=250VAC
XS1 XS2 XS3 XS4 XS5 XS6 XS7 XS8 XS10 XS11 XS12 XS13 XS14 XS15 XS16 XS17 XS18 XS19 XS20 XS21 XS22 XS23 XS24 XS25 XS26 XS27 XS28 XS29 XS30 XS31 XS32 XS33 XS34 XS35 XS36 XS37 XS38 XS39 XS40 XS41 XS42 XS43 XS44 XS45 XS46 XS47 XS48 XS49 XS50 XS51 XS52 XS53 XS54 XS55 XS56 XS57 XS58 XS59 XS60 XS61 XS62: library part Контр.точка, CurrentMax=3A

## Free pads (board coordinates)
  round 4 hole 2.2: 16(-90,-17) 16(-90,17) 16(-56,-17) 16(-56,17) 16(-49,-17) 16(-49,17) 16(-15,-17) 16(15,-17) 16(15,17) 16(49,-17) 16(56,-17) 16(56,17) 16(90,-17) 16(90,17)
  round 3.5 hole 2.2: 16(-15,17) 16(44,8) 16(49,8)
  rrect50% 9x4 hole 3 slot 8 at 0 deg: 16(0,-8) 16(0,8)
  round 3.8 hole 2.2: 16(49,17)

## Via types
v1: diameter 0.6, hole 0.3, Signal Layer 1 to Bottom Layer, tented both sides, 153 vias
v2: diameter 0.5, hole 0.25, Signal Layer 1 to Bottom Layer, tented both sides, 101 vias
v3: diameter 0.6, hole 0.3, Signal Layer 1 to Bottom Layer, 4 vias

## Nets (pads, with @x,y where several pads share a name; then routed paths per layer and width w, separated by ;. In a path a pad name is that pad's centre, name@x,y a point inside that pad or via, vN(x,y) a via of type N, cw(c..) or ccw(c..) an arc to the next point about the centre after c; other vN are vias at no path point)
170V: pad.16@49,-17 pad.16@90,-17 pad.16@-15,-17 R20.2 R21.2 R22.2 | length 187.1
  Signal Layer 1 w1: R20.2@43.913,-17.727 48.273,-17.727 pad.16@49,-17 ; R21.2@43.913,-15.727 pad.16@49,-17 ; R22.2@43.913,-13.727 pad.16@49,-17
  Bottom Layer w1.8: 6.863,-4.113 6.863,-8.863 8.287,-10.287 14.745,-10.287 22.195,-17.737 ; 9.241,-3.25 23.725,-17.734
  Bottom Layer w2: pad.16@-15,-17 -7.164,-9.026 -6.84,-5.013 ; 6,-3.25 6.863,-4.113
  Bottom Layer w2.5: -15.027,-8.085 -10.192,-3.25 6,-3.25 9.241,-3.25
  Bottom Layer w2.8: 23.198,-17.734 48.266,-17.734 pad.16@49,-17
  Bottom Layer w3: pad.16@48.567,-17.433 pad.16@49,-17
  Bottom Layer w3.5: -15.027,-8.085 -15.027,-14.475 -15,-14.502 pad.16@-15,-17 ; pad.16@49,-17 49,-14 52.5,-10.5 83.767,-10.5 pad.16@89.834,-16.566
+3.3V: C9.2 C10.2 C13.2 C15.2 C16.2 C17.2 C18.2 C19.2 C20.2 C21.2 C22.2 C23.2 C24.2 C25.2 C26.2 C29.2 C30.2 C31.2 C32.2 D2.2 D3.1 D3.5 D3.17 D4.1 D5.8 D6.1 DA1.2 DA2.4 DA2.5 R11.1 R12.1 R13.1 R14.1 R19.1 R27.2 R29.1 R30.2 R36.2 R37.2 R41.1 R42.1 R43.1 R44.1 XP5.6 XS29.1 | length 70.6
  Signal Layer 1 w0.2: v1@-70.203,13.102 v1(-70.157,13.148)
  Signal Layer 1 w0.3: -76.775,4.225 D2.2@-75.9,4.225 ; R19.1@-65.3,13.65 v1(-65.288,14.327) ; R42.1@-59.202,-0.132 v1(-58.481,-0.132) ; R43.1@-59.2,2.6 v1(-58.479,2.6) ; R44.1@-59.193,4.448 -59.093,4.426 v1(-58.472,4.426)
  Signal Layer 1 w0.4: v1(-81.848,-4.522) -81.014,-4.522 v1(-81.848,-3.689) ; v1(-80.985,-3.66) C21.2@-80.985,-4.522 C20.2@-79.485,-4.322 ; R14.1@-79.485,-3.222 C20.2@-79.485,-4.322 ; v1(-78.112,0.5) C9.2@-77.25,0.5 C10.2@-77.45,2 -77.45,3.55 -76.775,4.225 ; v1(-78.083,-0.362) -77.25,0.471 v1(-77.25,-0.362) ; DA1.2@-77.155,-4.325 -79.483,-4.325 C20.2@-79.485,-4.322 ; R27.2@-75.25,13.352 v1(-74.503,13.766) ; v1(-72.204,0.862) -71.371,0.862 v1(-72.204,1.696) ; C16.2@-71.342,0.862 v1(-71.342,1.724) ; C16.2@-71.334,0.805 C13.2@-69.994,1.009 D3.17@-69.5,2.5 D3.17@-69.5,2.298 ; v1(-70.217,13.853) -69.6,13.679 C19.2@-69.4,13.679 ; v1(-70.157,13.148) C19.2@-69.6,13.5 ; v1(-69.572,-1.509) R11.1@-68.891,-1.22 ; C19.2@-69.4,13.65 -68.5,12.8 C18.2@-68,12.75 C17.2@-67.1,12.75 D3.5@-67.1,11.1 ; v1(-66.187,-1.894) R13.1@-66.187,-1.224 ; v1(-64.388,-1.889) R12.1@-64.388,-1.219 ; D3.1@-63.9,11.1 -63.907,11.107 C15.2@-63.907,12.748 -62.721,12.748 C26.2@-62.649,12.82 ; v1(-58.481,-0.132) R41.1@-56.999,-0.132 ; v1(-43.01,-4.184) C31.2@-43.416,-3.69 C31.2@-43.332,-3.69 ; v1(-42.733,-3.091) C31.2@-43.332,-3.69 ; C32.2@-42.243,-3.69 C31.2@-43.332,-3.69 ; C32.2@-42.04,-3.679 -41.86,-3.5 D6.1@-40,-3.5 ; v1(-7.803,-17.384) R29.1@-7.8,-16.65 ; v1(-6.512,-12.4) -5.679,-12.4 v1(-6.512,-11.567) ; D4.1@-5.833,-14.733 C24.2@-5.85,-13.7 C22.2@-5.65,-12.4 v1(-5.65,-11.538) ; v1(-2.212,-16.11) -1.8,-15.75 R36.2@-1.75,-15.7 ; R37.2@-0.85,-18.5 -0.846,-18.504 v1(-0.046,-18.504) ; D5.8@5.39,-14.55 C25.2@7.05,-14.5 C23.2@6.75,-13.1 v1(6.75,-12.238) ; v1(5.888,-13.1) 6.721,-13.1 v1(5.888,-12.267) ; R30.2@7.95,-15.4 v1(8.673,-15.4)
  Signal Layer 1 w0.7: C26.2@-62.649,12.739 -61.672,11.761 -59.939,11.761 C30.2@-59.7,12 -59.097,11.397 ; DA2.5@-59.097,9.765 DA2.4@-59.097,10.592 -59.097,11.397 ; C29.2@-58.377,12.117 -59.097,11.397
  Signal Layer 1 w1: C26.2@-62.649,12.82 XS29.1@-62,15.2
  Bottom Layer w0.4: XP5.6@-70.758,17.5 -70.758,16.396 -71.5,15.654 -71.5,14.75 -70.603,13.853 v1(-70.217,13.853)
+5V: C4.2 C8.2 C11.2 C12.2 C27.2 C28.2 C35.2 C36.2 D1.6 D2.19 DA2.1 DA2.3 DA2.6 L1.2 pad.16@49,17 pad.16@-15,17 pad.16@-56,17 R4.1 XS7.1 XS34.1 XS40.1 | length 280.7
  Signal Layer 1 w0.2: 28.857,5.102 29.139,5.383 ccw(c28.997,5.525) 29.192,5.571 29.144,5.772 cw(c29.776,5.923) 29.142,5.78 29.002,6.4 D1.6@28.986,6.591
  Signal Layer 1 w0.3: D2.19@-82.1,4.225 -81.225,4.225 ; v1(-59.671,7.2) C28.2@-58.95,7.2 v1(-58.95,6.531)
  Signal Layer 1 w0.4: -81.225,4.225 -80.55,3.55 C11.2@-80.55,2 C12.2@-80.775,0.5 ; DA2.1@-56.197,8.692 C27.2@-54.6,8.55 v1(-53.738,8.55) ; DA2.3@-56.197,10.592 v1(-55.621,11.212) ; v1(-54.6,7.688) -54.6,8.521 v1(-53.767,7.688)
  Signal Layer 1 w0.5: DA2.6@-59.085,8.565 C28.2@-58.95,7.2
  Signal Layer 1 w0.8: XS7.1@-90,0.84 -87.74,0.84 -85.4,-1.5 -81.899,-1.5 -80.775,-0.376 C12.2@-80.775,0.5
  Signal Layer 1 w1: XS7.1@-90,0.84 -91.163,0.84 -92.157,1.834 -92.157,12.153 -90.953,13.357 -88.365,13.357 -86.5,15.222 -86.5,17.25 -85.45,18.3 -57.3,18.3 pad.16@-56,17
  Signal Layer 1 w2.3: pad.16@-56,17 -51.798,12.798 -46.216,12.798 -42.014,17 pad.16@-15,17 -6.9,17 -5.807,18.093 8.507,18.093 13.1,13.5 17.75,13.5 ; pad.16@48.732,17.268 pad.16@49,17
  Layer 2 w2.3: -52,12 -47,12 -41,18 -16,18 pad.16@-15,17
  Bottom Layer w0.3: R4.1@26.675,5.125 v2(27.281,4.648)
  Bottom Layer w1.5: XS34.1@-15,0.84 -14.466,0.84 -11.256,4.05 11.322,4.05 14.532,0.84 XS40.1@15,0.84 17.84,0.84 20,3 20,13 25.712,18.712 47.288,18.712 pad.16@49,17
BTN_1: R40.1 XP1.1 | length 21.6
  Signal Layer 1 w0.15: R40.1@-59.202,3.519 -58.158,3.519 -56.9,4.777 -48.493,4.777 -41.971,11.299 v1(-41.515,11.299)
  Bottom Layer w0.3: XP1.1@-41.515,10.578 v1(-41.515,11.299)
BTN_2: R39.1 XP2.1 | length 28.6
  Signal Layer 1 w0.15: R39.1@-59.194,1.688 -58.212,1.688 -57.804,2.096 -57.804,2.496 -56.027,4.273 -48.178,4.273 -41.921,10.53 -39.47,10.53 -38.701,11.299 v1(-35.515,11.299)
  Bottom Layer w0.3: XP2.1@-35.515,10.578 v1(-35.515,11.299)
